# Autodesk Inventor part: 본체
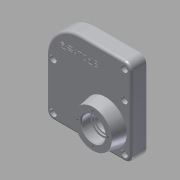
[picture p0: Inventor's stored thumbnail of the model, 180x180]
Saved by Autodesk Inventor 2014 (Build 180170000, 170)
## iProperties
Created: 2015-10
Part Number: 본체
Material: 알루미늄 6061
Document SubType Name: Modeling
Designer: youjin04
Density: 2.71 g/cm^3
Appearance: 알루미늄 - 평지
Mass: 243.448 g
Surface Area: 381.589 cm^2
Volume: 89.8331 cm^3
Author: youjin04
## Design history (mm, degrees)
sketch "스케치1"
  geometry: L1 (-52, -63)-(32, -63); L2 (40, -55)-(40, 0); L3 (0, 40)-(-52, 40); L4 (-60, -63)-(40, 40); L5 (40, -63)-(-60, 40); L6 (-28, -63)-(-28, -59); L7 (-28, -59)-(27.528, -59); L8 (-28, -59)-(-47.528, -59); L9 (40, -35)-(36, -35); L10 (36, -35)-(36, -50.528); L11 (36, -35)-(36, -4.472); L12 (-60, -25)-(-56, -25); L13 (-56, 17)-(-56, 27.528); L14 (-56, 17)-(-56, 4.472); L15 (-56, -25)-(-56, -4.472); L16 (-56, -25)-(-56, -50.528); L17 (-30, 36)-(-47.528, 36); L18 (-30, 36)-(-17.436, 36); L19 (-17.436, 36)-(0, 36); L20 (32, -6)-(40, -6); L21 (32, 6)-(39.547, 6); L22 (-52, 6)-(-60, 6); L23 (-52, -6)-(-60, -6); L24 (-52, -49)-(-60, -49); L25 (-46, -55)-(-46, -63); L26 (-52, 26)-(-60, 26); L27 (-46, 32)-(-46, 40); L28 (26, -55)-(26, -63); L29 (32, -49)-(40, -49); C1 r 2.25 at (-52, 32); C2 r 2.25 at (-52, -55); C3 r 2.25 at (32, -55); C4 r 2.25 at (-52, 0); C5 r 2.25 at (32, 0); A1 r 8 centre (-52, 32) between (-52, 40) and (-60, 32); A2 r 8 centre (-52, -55) between (-60, -55) and (-52, -63); A3 r 8 centre (32, -55) between (32, -63) and (40, -55); A4 r 6 centre (-52, 32) between (-56, 27.528) and (-47.528, 36); A5 r 6 centre (-52, 0) between (-56, -4.472) and (-56, 4.472); A6 r 6 centre (-52, -55) between (-47.528, -59) and (-56, -50.528); A7 r 6 centre (32, -55) between (36, -50.528) and (27.528, -59); A8 r 6 centre (32, 0) between (35.688, 4.733) and (36, -4.472); A9 r 40 centre (0, 0) between (40, 0) and (0, 40); A10 r 36 centre (0, 0) between (35.688, 4.733) and (0, 36); 2 further points; 1 other entity
  constraints: 58 end point, 31 point on circle, 17 tangent, 15 centre point, 11 coincident, 11 perpendicular, 11 point on line, 6 collinear, 4 horizontal, 4 parallel, 4 vertical alignment, 3 horizontal alignment, 2 equal radius, 2 midpoint, 1 vertical, 12 other
  dimensions: "d3" = 100 distance of L5.end L4.end; "d4" = 103 distance of L4.end L5.start; "d8" = 8 radius of A1; "d9" = 4.5 diameter of C1; "d10" = 4.5 diameter of C2; "d11" = 4.5 diameter of C3; "d12" = 4.5 diameter of C4; "d14" = 4.5 diameter of C5; "d16" = 6 radius of A4; "d17" = 6 radius of A5; "d18" = 6 radius of A6; "d19" = 6 radius of A7; "d20" = 6 radius of A8; "d21" = 4 distance of L6.start L6.end; "d22" = 4 distance of L9.start L9.end; "d23" = 4 distance of L12.start L12.end
extrude "돌출2" join sketch "스케치1" distance "d24" = 18; taper "d25" = 0 deg
extrude "돌출3" join sketch "스케치1" distance "d26" = 4; taper "d27" = 0 deg
sketch "스케치2"
  geometry: L1 (-52, -63)-(32, -63) reference; L2 (-60, 32)-(-60, -55) reference; C1 r 10 at (-30, -33)
  constraints: 1 centre point
  dimensions: "d29" = 20 diameter of C1; "d30" = 30 distance from line of C1.centre L1; "d31" = 30 distance from line of C1.centre L2
extrude "돌출4" cut sketch "스케치2" distance "d32" = 4; taper "d33" = 0 deg
sketch "스케치3"
  geometry: C1 r 10 at (30, -33) reference; C2 r 25 at (30, -33)
  constraints: 1 centre point, 1 coincident
  dimensions: "d34" = 50 diameter of C2
extrude "돌출5" join sketch "스케치3" distance "d35" = 15; taper "d36" = -10 deg
sketch "스케치4"
  geometry: C1 r 22.355 at (0, 0) reference; A1 r 18 centre (0, 0) between (0, 18) and (-18, 0); 3 further points
  constraints: 4 point on circle, 1 centre point, 1 coincident
  dimensions: "d37" = 36 diameter of A1
hole "구멍1" sketch "스케치4" at (0, 18), (-18, 0), (0, -18), (18, 0) diameter "d38" = 2.459; stored, may be unused: countersink angle "d42" = 90 deg, drill point angle "d44" = 118 deg; dims "d39" = 8, "d40" = 4, "d41" = 2, "d43" = 10
sketch "스케치5"
  geometry: L1 (-40, -55)-(-40, 0) reference; L2 (52, -63)-(-32, -63) reference; L3 (60, 32)-(60, -55) reference; L4 (0, 40)-(52, 40) reference; C1 r 25 at (30, -33) reference; C2 r 2.25 at (-32, 0) reference; C3 r 2.25 at (52, 0) reference; C4 r 2.25 at (52, 32) reference; C5 r 2.25 at (-32, -55) reference; C6 r 2.25 at (52, -55) reference; A1 r 8 centre (-32, -55) between (-40, -55) and (-32, -63) reference; A2 r 8 centre (52, -55) between (52, -63) and (60, -55) reference; A3 r 8 centre (52, 32) between (60, 32) and (52, 40) reference; A4 r 40 centre (0, 0) between (0, 40) and (-40, 0) reference
fillet "모깎기1" dims "d45" = 3
fillet "모깎기2" dims "d46" = 3
sketch "스케치8"
  geometry: C1 r 1.23 at (0, -18) reference; C2 r 1.23 at (0, 18) reference; C3 r 1.23 at (-18, 0) reference; C4 r 1.23 at (18, 0) reference; C5 r 12.645 at (0, 0) reference; C6 r 22.355 at (0, 0) reference; 1 further point
sketch "스케치9"
  geometry: C1 r 10 at (-30, -33) reference; C2 r 16 at (-30, -33)
  constraints: 1 centre point, 1 coincident
  dimensions: "d52" = 32 diameter of C2
sketch "스케치11"
  geometry: C1 r 2.25 at (-32, 0) reference; C2 r 2.25 at (52, 0) reference; C3 r 2.25 at (52, 32) reference; C4 r 2.25 at (-32, -55) reference; C5 r 2.25 at (52, -55) reference; C6 r 4 at (-32, 0); C7 r 4 at (-32, -55); C8 r 4 at (52, -55); C9 r 4 at (52, 0); C10 r 4 at (52, 32); A1 r 8 centre (-32, -55) between (-40, -55) and (-32, -63) reference; A2 r 8 centre (52, -55) between (52, -63) and (60, -55) reference; A3 r 8 centre (52, 32) between (60, 32) and (52, 40) reference
  constraints: 5 centre point, 5 coincident
  dimensions: "d61" = 8 diameter of C6; "d62" = 8 diameter of C7; "d63" = 8 diameter of C8; "d64" = 8 diameter of C9; "d65" = 8 diameter of C10
extrude "돌출9" cut sketch "스케치11" distance "d66" = 4.4; taper "d67" = 0 deg
sketch "스케치12"
  geometry: C1 r 22.355 at (0, 0) reference; C2 r 14 at (0, 0); C3 r 12 at (0, 0); 1 further point
  constraints: 2 centre point, 2 coincident
  dimensions: "d68" = 28 diameter of C2; "d69" = 24 diameter of C3
extrude "돌출10" cut sketch "스케치12" distance "d70" = 13; taper "d71" = 0 deg
extrude "돌출11" cut sketch "스케치12" distance "d72" = 11; taper "d73" = 0 deg
sketch "스케치13"
  geometry: L1 (-40, -55)-(-40, 0) reference; L2 (0, 40)-(52, 40) reference; 2 further points
  constraints: 1 coincident, 1 other
  dimensions: "d74" = 40 distance from line of point (0, 20) L1; "d75" = 20 distance from line of point (0, 20) L2
feature "엠보싱1" sketch "스케치13" dims "d76" = 0.5, "d77" = 0
fillet "모깎기4" dims "d78" = 3
chamfer "모따기1" distance "d79" = 1; stored, may be unused: second distance "d80" = 2, angle "d81" = 45 deg
sketch "스케치14"
  geometry: C1 r 16 at (0, 0); C2 r 11 at (0, 0); A1 r 33 centre (0, 0) between (31.75, 8.997) and (0, 33) reference
  constraints: 2 centre point, 2 coincident
  dimensions: "d82" = 32 diameter of C1; "d83" = 22 diameter of C2
extrude "돌출12" join sketch "스케치14" distance "d84" = 9; taper "d85" = 0 deg
fillet "모깎기5" dims "d86" = 3
extrude "돌출13" join sketch "스케치9" distance "d87" = 9; taper "d88" = 0 deg
chamfer "모따기2" distance "d89" = 1; stored, may be unused: second distance "d90" = 2, angle "d91" = 45 deg
sketch "스케치15"
  geometry: C1 r 16 at (0, 0) reference; C2 r 11 at (0, 0) reference; 1 further point
node "솔리드1"
other parameters: "d5" = 36
